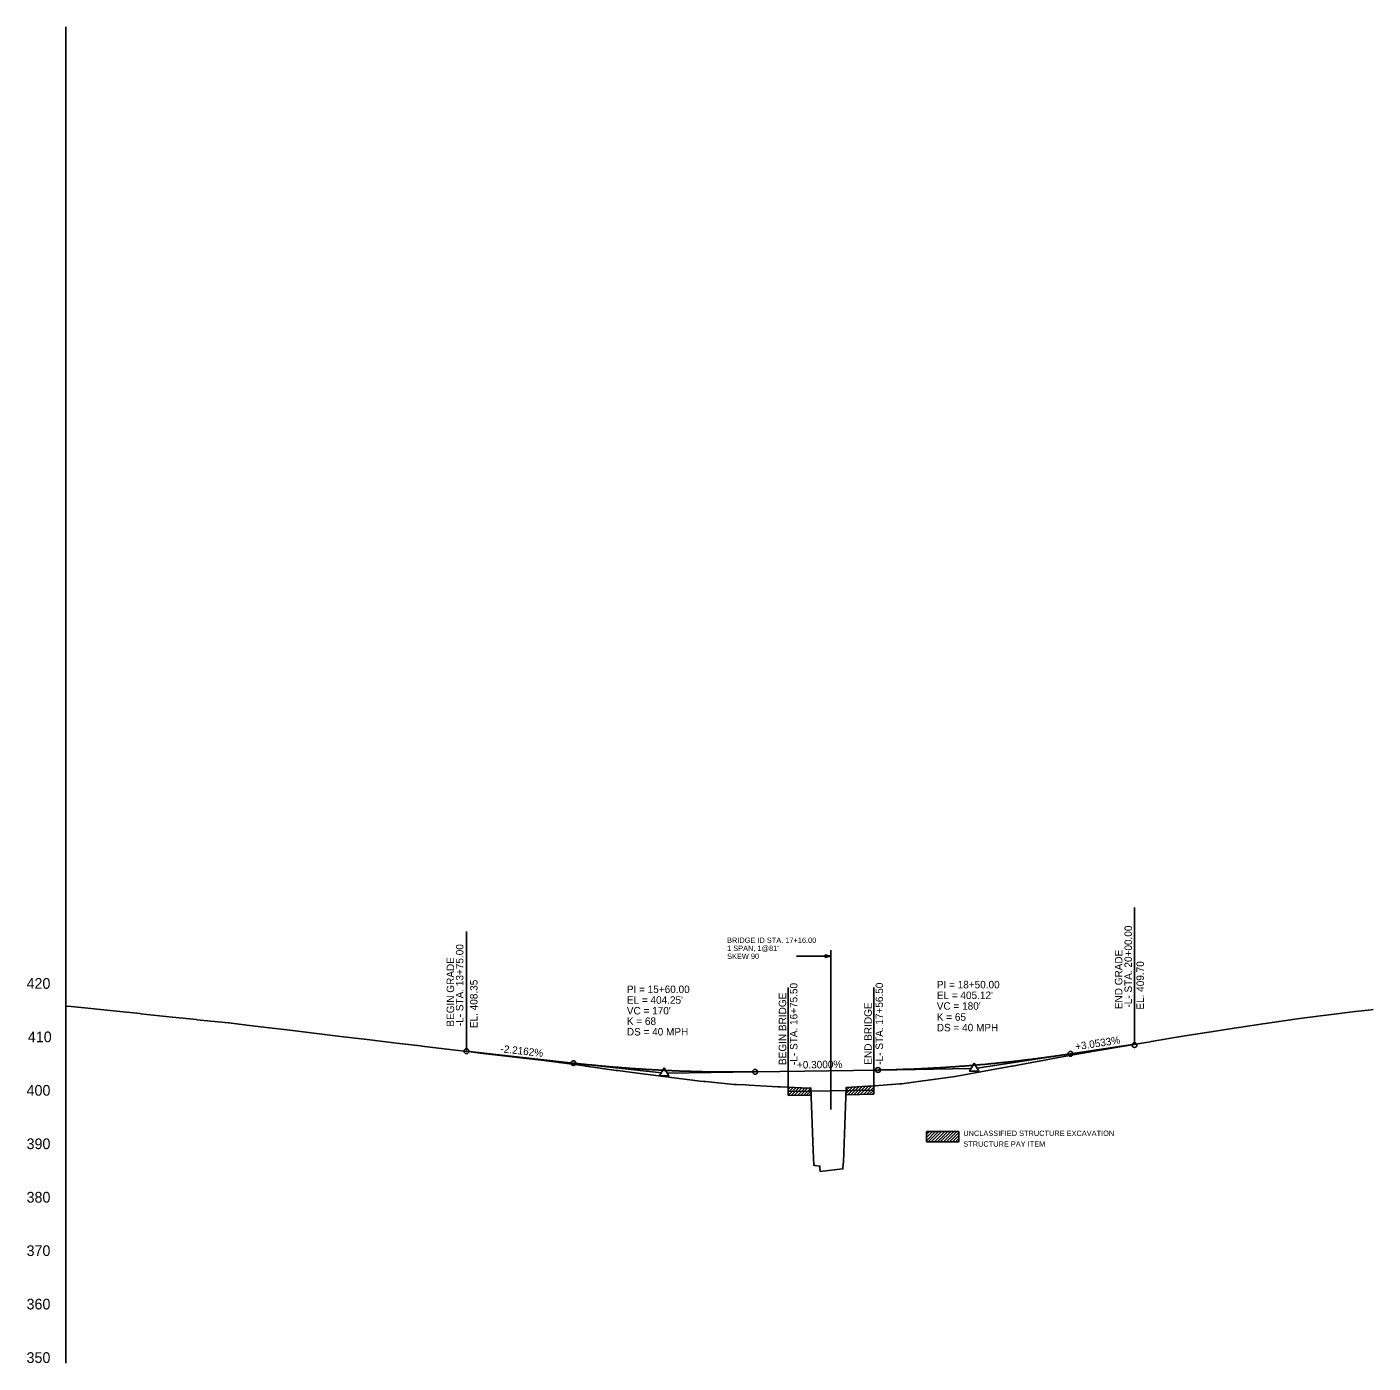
# Model space of a CAD drawing. Extents: x 99964 to 101300, y 93750 to 101250.
# Drawn here: x 99964 to 101223, y 100000 to 101250 of the extents above; entities that cross this region are included whole.
import ezdxf

# ---------------------------------------------------------------- set-up
doc = ezdxf.new("R2010")
doc.units = 0
for name, color, linetype in [('Exist Vertical Profile Ground Line', 7, 'Continuous'), ('Exist Vertical Profile Vertical Axis Label', 7, 'Continuous'), ('Old_Level_63', 7, 'Continuous'), ('Prop PFL Text', 7, 'Continuous'), ('Prop Vertical Profile Curve Label', 7, 'Continuous'), ('Prop Vertical Profile Grade', 7, 'Continuous'), ('Prop Vertical Profile Grade Label', 7, 'Continuous'), ('Prop VPI Label', 7, 'Continuous')]:
    doc.layers.add(name, color=color, linetype=linetype)

msp = doc.modelspace()

# ---------------------------------------------------------------- linework, layer by layer
at = {"layer": 'Exist Vertical Profile Ground Line'}
for points in [[(100000, 100334), (100005.2, 100333.5), (100017.5, 100332.3), (100017.5, 100332.3), (100047.4, 100329.4), (100047.5, 100329.3), (100069.7, 100327), (100070, 100326.9), (100099.6, 100323.7), (100099.9, 100323.7), (100122.3, 100321.4), (100122.7, 100321.3), (100152.3, 100318.2), (100152.6, 100318.2), (100174.5, 100315.6), (100174.7, 100315.6), (100193.1, 100313.4), (100204.5, 100312), (100204.6, 100312), (100227.1, 100309.3), (100227.3, 100309.2), (100257, 100305.7), (100257.2, 100305.6), (100279.3, 100303), (100279.5, 100303), (100309.4, 100299.4), (100309.4, 100299.4), (100331.9, 100296.7), (100331.9, 100296.7), (100333.3, 100296.6), (100361.9, 100293.1), (100361.9, 100293.1), (100378.9, 100291.1), (100387.8, 100290.1), (100387.8, 100290.1), (100417.7, 100286.6), (100417.8, 100286.6), (100442, 100283.6), (100442.6, 100283.6), (100471.3, 100280), (100472.4, 100279.9), (100476.5, 100279.3), (100485.3, 100278.1), (100486.9, 100277.8), (100515.1, 100273.9), (100516.6, 100273.7), (100535, 100271.3), (100537.4, 100271), (100564.7, 100267.5), (100566.9, 100267.2), (100593.6, 100263.8), (100597, 100263.5), (100598.5, 100263.4), (100625.1, 100260.8), (100627.6, 100260.6), (100636.2, 100260.2), (100639.6, 100259.9), (100666.3, 100258.6), (100668.4, 100258.4), (100695.3, 100257.1), (100697.3, 100257.4), (100699.3, 100198.9), (100699.9, 100185.1), (100700.9, 100185), (100705.7, 100184.3), (100705.7, 100182.8), (100705.8, 100179.4), (100726.8, 100181.7), (100727.1, 100181.7), (100727.1, 100181.7), (100727.5, 100186.5), (100727.6, 100187.9), (100730.1, 100257.8), (100750.4, 100259.2), (100753.1, 100259.2), (100780.4, 100261.2), (100780.7, 100261.2), (100782.3, 100261.4), (100802, 100264.1), (100804.6, 100264.4), (100832.3, 100268.2), (100833.8, 100268.5), (100854.3, 100272.2), (100856, 100272.5), (100884.9, 100277.7), (100885.6, 100277.9), (100893.8, 100279.4), (100908.8, 100282.2), (100909.1, 100282.3), (100924, 100285.1), (100939, 100287.8), (100939.2, 100287.8), (100962.3, 100291.8), (100991.9, 100296.9), (100992.3, 100296.9), (101006.9, 100299.4), (101014.8, 100300.7), (101015.2, 100300.8), (101015.6, 100300.9), (101045.2, 100305.8), (101067.4, 100309.3)], [(101067.4, 100309.3), (101067.7, 100309.3), (101097.3, 100313.9), (101097.7, 100314), (101122.1, 100317.6), (101122.4, 100317.7), (101152.1, 100322.1), (101152.3, 100322.1), (101176.4, 100325.1), (101176.8, 100325.1), (101206.5, 100328.8), (101206.7, 100328.8), (101206.8, 100328.8), (101221.3, 100330.5), (101221.5, 100330.5), (101223.2, 100330.7)]]:
    msp.add_lwpolyline(points, dxfattribs=at)
at = {"layer": 'Old_Level_63'}
msp.add_line((100000, 100000), (100000, 101250), dxfattribs=at)
at = {"layer": 'Prop PFL Text'}
for p, q in [((100683.8, 100380.8), (100716, 100380.8)), ((100716, 100237.4), (100716, 100386.2)), ((100676, 100256), (100677.9, 100257.9)), ((100676, 100253.2), (100680.6, 100257.8)), ((100676, 100250.3), (100683.3, 100257.7)), ((100676, 100254.2), (100676, 100250.3)), ((100676, 100250.3), (100697.6, 100250.7)), ((100678.9, 100250.4), (100686, 100257.5)), ((100681.7, 100250.4), (100688.7, 100257.4)), ((100684.6, 100250.5), (100691.4, 100257.3)), ((100687.5, 100250.5), (100694.1, 100257.1)), ((100690.4, 100250.5), (100697.1, 100257.3)), ((100693.2, 100250.6), (100697.4, 100254.8)), ((100696.1, 100250.6), (100697.5, 100252.1)), ((100729.8, 100251.9), (100736.2, 100258.2)), ((100729.8, 100251.1), (100756, 100251.5)), ((100729.9, 100254.8), (100733.1, 100258)), ((100732, 100251.2), (100739.2, 100258.4)), ((100734.8, 100251.2), (100742.3, 100258.7)), ((100737.7, 100251.3), (100745.3, 100258.9)), ((100740.6, 100251.3), (100748.4, 100259.1)), ((100743.4, 100251.3), (100751.4, 100259.3)), ((100746.3, 100251.4), (100754.3, 100259.4)), ((100749.2, 100251.4), (100756, 100258.2)), ((100752.1, 100251.5), (100756, 100255.4)), ((100754.9, 100251.5), (100756, 100252.6)), ((100756, 100251.5), (100756, 100255.4)), ((100805.4, 100208.1), (100813.9, 100216.6)), ((100805.4, 100211), (100811, 100216.6)), ((100805.4, 100213.8), (100808.2, 100216.6)), ((100807, 100207), (100816.7, 100216.6)), ((100809.8, 100207), (100819.5, 100216.6)), ((100812.7, 100207), (100822.4, 100216.6)), ((100815.5, 100207), (100825.2, 100216.6)), ((100818.3, 100207), (100828, 100216.6)), ((100821.2, 100207), (100830.8, 100216.6)), ((100824, 100207), (100833.7, 100216.6)), ((100826.8, 100207), (100835.6, 100215.8)), ((100829.6, 100207), (100835.6, 100212.9)), ((100832.5, 100207), (100835.6, 100210.1)), ((100835.3, 100207), (100835.6, 100207.3))]:
    msp.add_line(p, q, dxfattribs=at)
for points in [[(100710.7, 100382.1), (100716, 100380.8), (100710.7, 100379.5)], [(100835.6, 100216.6), (100805.4, 100216.6), (100805.4, 100207), (100835.6, 100207)]]:
    msp.add_lwpolyline(points, close=True, dxfattribs=at)
at = {"layer": 'Prop Vertical Profile Curve Label'}
for centre in [(100375, 100291.8), (100940, 100289.3), (101000, 100297.5), (100475, 100280.7), (100760, 100274.2), (100645, 100272.5)]:
    msp.add_circle(centre, 2.25, dxfattribs=at)
at = {"layer": 'Prop Vertical Profile Grade'}
for p, q in [((100375, 100291.8), (100475, 100280.7)), ((100940, 100289.3), (101000, 100298.5)), ((100645, 100272.5), (100760, 100274.2)), ((100676, 100254.2), (100676, 100273)), ((100756, 100255.4), (100756, 100274.2)), ((100676, 100254.2), (100756, 100255.4))]:
    msp.add_line(p, q, dxfattribs=at)
for points in [[(100760, 100274.2), (100763.6, 100274.3), (100767.2, 100274.4), (100770.8, 100274.5), (100774.4, 100274.5), (100778, 100274.6), (100781.6, 100274.8), (100785.2, 100274.9), (100788.8, 100275), (100792.4, 100275.1), (100796, 100275.3), (100799.6, 100275.4), (100803.2, 100275.6), (100806.8, 100275.8), (100810.4, 100276), (100814, 100276.2), (100817.6, 100276.4), (100821.2, 100276.6), (100824.8, 100276.8), (100828.4, 100277.1), (100832, 100277.3), (100835.6, 100277.6), (100839.2, 100277.8), (100842.8, 100278.1), (100846.4, 100278.4), (100850, 100278.7), (100853.6, 100279), (100857.2, 100279.3), (100860.8, 100279.6), (100864.4, 100280), (100868, 100280.3), (100871.6, 100280.7), (100875.2, 100281.1), (100878.8, 100281.4), (100882.4, 100281.8), (100886, 100282.2), (100889.6, 100282.6), (100893.2, 100283), (100896.8, 100283.5), (100900.4, 100283.9), (100904, 100284.3), (100907.6, 100284.8), (100911.2, 100285.3), (100914.8, 100285.7), (100918.4, 100286.2), (100922, 100286.7), (100925.6, 100287.2), (100929.2, 100287.7), (100932.8, 100288.3), (100936.4, 100288.8), (100940, 100289.3)], [(100475, 100280.7), (100478.4, 100280.3), (100481.8, 100279.9), (100485.2, 100279.6), (100488.6, 100279.2), (100492, 100278.9), (100495.4, 100278.6), (100498.8, 100278.2), (100502.2, 100277.9), (100505.6, 100277.6), (100509, 100277.3), (100512.4, 100277), (100515.8, 100276.8), (100519.2, 100276.5), (100522.6, 100276.2), (100526, 100276), (100529.4, 100275.7), (100532.8, 100275.5), (100536.2, 100275.3), (100539.6, 100275.1), (100543, 100274.8), (100546.4, 100274.6), (100549.8, 100274.5), (100553.2, 100274.3), (100556.6, 100274.1), (100560, 100273.9), (100563.4, 100273.8), (100566.8, 100273.6), (100570.2, 100273.5), (100573.6, 100273.3), (100577, 100273.2), (100580.4, 100273.1), (100583.8, 100273), (100587.2, 100272.9), (100590.6, 100272.8), (100594, 100272.7), (100597.4, 100272.6), (100600.8, 100272.6), (100604.2, 100272.5), (100607.6, 100272.5), (100611, 100272.4), (100614.4, 100272.4), (100617.8, 100272.4), (100621.2, 100272.4), (100624.6, 100272.4), (100628, 100272.4), (100631.4, 100272.4), (100634.8, 100272.4), (100638.2, 100272.4), (100641.6, 100272.5), (100645, 100272.5)]]:
    msp.add_spline(points, degree=3, dxfattribs=at)
at = {"layer": 'Prop VPI Label'}
for p, q in [((101000, 100299.8), (101000, 100426.3)), ((100375, 100291.8), (100375, 100403.9)), ((100676, 100273), (100676, 100351.3)), ((100756, 100274.2), (100756, 100351.3)), ((100940, 100289.3), (100852.7, 100276)), ((100475, 100280.7), (100557.3, 100271.6)), ((100645, 100272.5), (100562.7, 100271.3)), ((100760, 100274.2), (100847.3, 100275.6))]:
    msp.add_line(p, q, dxfattribs=at)
for points in [[(100560, 100276.2), (100555.7, 100268.8), (100564.3, 100268.8)], [(100850, 100280.6), (100845.7, 100273.1), (100854.3, 100273.1)]]:
    msp.add_lwpolyline(points, close=True, dxfattribs=at)

# ---------------------------------------------------------------- texts
at = {"layer": 'Exist Vertical Profile Vertical Axis Label'}
for s, p in [('420', (99963.4, 100350.2)), ('410', (99964.6, 100300.2)), ('400', (99963.4, 100250.2)), ('390', (99963.4, 100200.2)), ('380', (99963.4, 100150.2)), ('370', (99963.4, 100100.2)), ('360', (99963.4, 100050.2)), ('350', (99963.4, 100000.2))]:
    msp.add_text(s, height=10, dxfattribs=at).set_placement(p)
at = {"layer": 'Prop PFL Text'}
for s, p in [('BRIDGE ID STA. 17+16.00', (100618.8, 100393.1)), ("1 SPAN, 1@81'", (100618.8, 100385.6)), ('SKEW 90', (100618.8, 100378.1)), ('UNCLASSIFIED STRUCTURE EXCAVATION', (100839.8, 100212.5)), ('STRUCTURE PAY ITEM', (100839.8, 100202.5))]:
    msp.add_text(s, height=5, rotation=360, dxfattribs=at).set_placement(p)
at = {"layer": 'Prop Vertical Profile Curve Label'}
for s, p in [("VC = 170'", (100525, 100326.2)), ("VC = 180'", (100815, 100330.6)), ('K = 65', (100815, 100320.3)), ('K = 68', (100525, 100316.4)), ('DS = 40 MPH', (100525, 100306.5)), ('DS = 40 MPH', (100815, 100310.4))]:
    msp.add_text(s, height=7, dxfattribs=at).set_placement(p)
at = {"layer": 'Prop Vertical Profile Grade Label'}
for s, rotation, p in [('+3.0533%', 8.6801, (100945, 100292.6)), ('-2.2162%', 353.6768, (100406.5, 100290.8)), ('+0.3000%', 0.8594, (100684.2, 100275.5))]:
    msp.add_text(s, height=7, rotation=rotation, dxfattribs=at).set_placement(p)
at = {"layer": 'Prop VPI Label'}
for s, p in [('-L- STA. 20+00.00', (100997.6, 100332.6)), ('-L- STA. 13+75.00', (100372.1, 100315.2)), ('BEGIN GRADE', (100363.4, 100314.8)), ('END GRADE', (100988.6, 100331.1)), ('EL. 409.70', (101008.8, 100330.7)), ('EL. 408.35', (100385.3, 100313.4)), ('-L- STA. 16+75.50', (100684.6, 100278.9)), ('-L- STA. 17+56.50', (100764.7, 100279.2)), ('BEGIN BRIDGE', (100674.1, 100278.9)), ('END BRIDGE', (100754.2, 100279.2))]:
    msp.add_text(s, height=7, rotation=90, dxfattribs=at).set_placement(p)
for s, p in [('PI = 15+60.00', (100525, 100346.2)), ('PI = 18+50.00', (100815, 100350.6)), ("EL = 404.25'", (100525, 100336.2)), ("EL = 405.12'", (100815, 100340.6))]:
    msp.add_text(s, height=7, dxfattribs=at).set_placement(p)

doc.saveas('drawing.dxf')
